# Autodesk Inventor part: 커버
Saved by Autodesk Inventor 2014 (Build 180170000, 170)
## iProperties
Created: 2025-12
Part Number: 커버
Material: 일반
Document SubType Name: Modeling
Designer: dg
Density: 1 g/cm^3
Appearance: 기본값
Author: dg
Author: jhkim
Creation Date: 2025-11-19
Sending System: Autodesk Inventor 2026
Preprocessor: ST-DEVELOPER v20.1
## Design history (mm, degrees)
node "커버1"
node "솔리드1"
node "기준1"
